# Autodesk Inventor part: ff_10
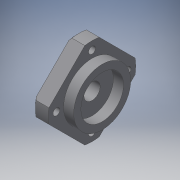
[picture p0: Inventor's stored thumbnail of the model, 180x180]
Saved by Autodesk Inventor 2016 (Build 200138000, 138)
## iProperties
Company: TraceParts S.A.
Created: 2016-12
Part Number: ff_10
Checked By: TraceParts S.A.
Catalog Web Link: www.traceparts.com
Document SubType Name: Modeling
Designer: TraceParts
Material: Типовые
Density: 1 g/cm^3
Appearance: По умолчанию
Mass: 8.61137 g
Surface Area: 44.74 cm^2
Volume: 8.61137 cm^3
REFERENCE: FF 10
DESIGN: Свободная опора FF
SUPPLIER: Technische Antriebselemente GmbH - Germany
TraceParts.PartNumber: 80-08072009-855310
TraceParts.PartTitle: Свободная опора FF
TraceParts.InstanceId: 80-08072009-855310B0GE3FYSM0UW8021YVT61FMK3
TraceParts.PartStatus: Published
TraceParts.PartVersion: 1.0.7
TRACEPARTS: TRACEPARTS
TraceParts.PartLanguage: ru
TraceParts.ClassPath: TEA_GER:/TEA_GER.1/TEA.120/TEA.120.020/80-08072009-855310
Author: TraceParts
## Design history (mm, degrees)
feature "ff_10"
node "Твердое тело1"
node "Твердые тела"
node "Поверхностные тела"
